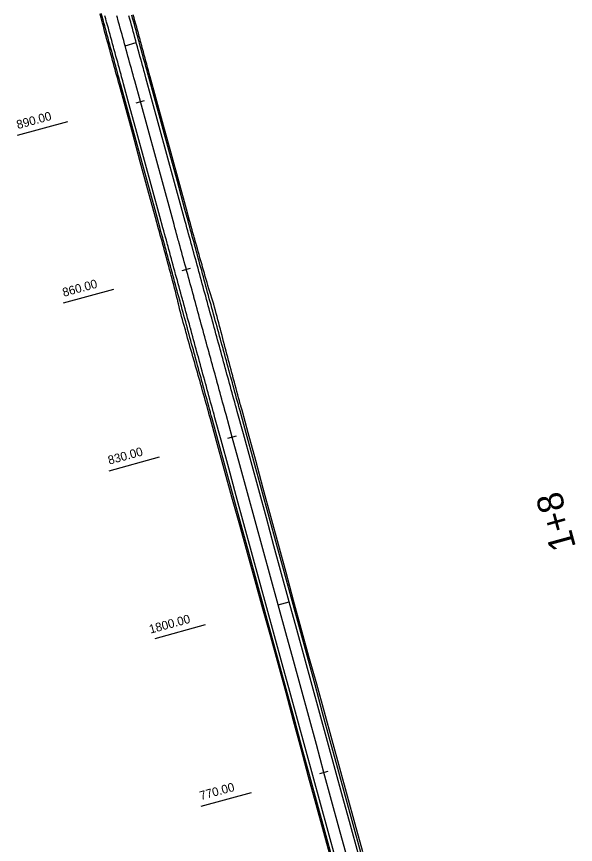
# Model space of a CAD drawing. Extents: x -550605 to -538780, y -1102367 to -1093705.
# Drawn here: x -547558.2 to -547461.7, y -1100514.3 to -1100371.5 of the extents above; entities that cross this region are included whole.
import ezdxf

# ---------------------------------------------------------------- set-up
doc = ezdxf.new("R2010")
doc.units = 0
for name, color, linetype in [('SIT - hrany vozovky', 7, 'Continuous'), ('SIT - osa cesty', 7, 'Continuous'), ('SIT - paty násypů', 7, 'Continuous'), ('SIT - staničení po 100m', 7, 'Continuous'), ('SIT - staničení po 30m', 7, 'Continuous')]:
    doc.layers.add(name, color=color, linetype=linetype)

msp = doc.modelspace()

# ---------------------------------------------------------------- linework, layer by layer
at = {"layer": 'SIT - hrany vozovky'}
for points in [[(-547503.59, -1100517.03), (-547504.91, -1100512.21), (-547506.23, -1100507.39), (-547507.55, -1100502.56), (-547508.87, -1100497.74), (-547510.19, -1100492.92), (-547511.51, -1100488.09), (-547512.83, -1100483.27), (-547514.15, -1100478.45), (-547515.47, -1100473.63), (-547516.79, -1100468.8), (-547518.11, -1100463.98), (-547519.43, -1100459.16), (-547520.74, -1100454.34), (-547522.06, -1100449.51), (-547523.38, -1100444.69), (-547524.44, -1100440.83), (-547524.59, -1100440.29), (-547524.7, -1100439.87), (-547524.74, -1100439.75), (-547524.88, -1100439.22), (-547525.03, -1100438.68), (-547525.18, -1100438.14), (-547525.32, -1100437.6), (-547525.47, -1100437.07), (-547525.62, -1100436.53), (-547525.77, -1100435.99), (-547525.91, -1100435.45), (-547526.02, -1100435.05), (-547526.06, -1100434.92), (-547526.21, -1100434.38), (-547526.35, -1100433.84), (-547526.5, -1100433.3), (-547526.65, -1100432.77), (-547526.8, -1100432.23), (-547526.94, -1100431.69), (-547527.09, -1100431.15), (-547527.24, -1100430.62), (-547527.34, -1100430.22), (-547527.38, -1100430.08), (-547527.53, -1100429.54), (-547527.68, -1100429), (-547527.83, -1100428.47), (-547527.97, -1100427.93), (-547528.12, -1100427.39), (-547528.27, -1100426.85), (-547528.41, -1100426.32), (-547528.56, -1100425.78), (-547528.66, -1100425.4), (-547528.71, -1100425.24), (-547528.86, -1100424.7), (-547529, -1100424.17), (-547529.15, -1100423.63), (-547529.3, -1100423.09), (-547529.44, -1100422.56), (-547529.59, -1100422.02), (-547529.74, -1100421.48), (-547529.88, -1100420.94), (-547529.98, -1100420.58), (-547530.03, -1100420.41), (-547530.18, -1100419.87), (-547530.33, -1100419.33), (-547530.47, -1100418.79), (-547530.62, -1100418.26), (-547530.77, -1100417.72), (-547530.91, -1100417.18), (-547531.06, -1100416.64), (-547531.21, -1100416.11), (-547531.3, -1100415.76), (-547531.36, -1100415.57), (-547531.5, -1100415.03), (-547531.65, -1100414.49), (-547531.8, -1100413.96), (-547531.94, -1100413.42), (-547532.09, -1100412.88), (-547532.24, -1100412.34), (-547532.39, -1100411.81), (-547532.53, -1100411.27), (-547532.62, -1100410.93), (-547532.68, -1100410.73), (-547532.83, -1100410.19), (-547532.97, -1100409.66), (-547533.12, -1100409.12), (-547533.27, -1100408.58), (-547533.42, -1100408.04), (-547533.94, -1100406.11), (-547535.26, -1100401.29), (-547536.58, -1100396.47), (-547537.9, -1100391.64), (-547539.22, -1100386.82), (-547540.2, -1100383.25), (-547540.35, -1100382.71), (-547540.49, -1100382.18), (-547540.54, -1100382), (-547540.64, -1100381.64), (-547540.79, -1100381.11), (-547540.93, -1100380.58), (-547541.08, -1100380.04), (-547541.23, -1100379.51), (-547541.37, -1100378.97), (-547541.52, -1100378.44), (-547541.66, -1100377.91), (-547541.81, -1100377.37), (-547541.86, -1100377.17), (-547541.96, -1100376.84), (-547542.1, -1100376.3), (-547542.25, -1100375.77), (-547542.39, -1100375.24), (-547542.54, -1100374.7), (-547542.69, -1100374.17), (-547542.83, -1100373.63), (-547542.98, -1100373.1), (-547543.13, -1100372.57), (-547543.18, -1100372.35), (-547543.27, -1100372.03), (-547543.42, -1100371.5), (-547543.56, -1100370.97)], [(-547503.1, -1100516.9), (-547504.42, -1100512.08), (-547505.74, -1100507.25), (-547507.06, -1100502.43), (-547508.38, -1100497.61), (-547509.7, -1100492.79), (-547511.02, -1100487.96), (-547512.34, -1100483.14), (-547513.66, -1100478.32), (-547514.98, -1100473.5), (-547516.3, -1100468.67), (-547517.62, -1100463.85), (-547518.94, -1100459.03), (-547520.26, -1100454.2), (-547521.58, -1100449.38), (-547522.9, -1100444.56), (-547523.96, -1100440.7), (-547524.11, -1100440.16), (-547524.22, -1100439.74), (-547524.25, -1100439.62), (-547524.4, -1100439.09), (-547524.55, -1100438.55), (-547524.7, -1100438.01), (-547524.84, -1100437.47), (-547524.99, -1100436.94), (-547525.14, -1100436.4), (-547525.28, -1100435.86), (-547525.43, -1100435.32), (-547525.54, -1100434.91), (-547525.58, -1100434.79), (-547525.72, -1100434.25), (-547525.87, -1100433.71), (-547526.02, -1100433.17), (-547526.17, -1100432.64), (-547526.31, -1100432.1), (-547526.46, -1100431.56), (-547526.61, -1100431.02), (-547526.75, -1100430.49), (-547526.86, -1100430.09), (-547526.9, -1100429.95), (-547527.05, -1100429.41), (-547527.2, -1100428.87), (-547527.34, -1100428.34), (-547527.49, -1100427.8), (-547527.64, -1100427.26), (-547527.78, -1100426.72), (-547527.93, -1100426.19), (-547528.08, -1100425.65), (-547528.18, -1100425.27), (-547528.23, -1100425.11), (-547528.37, -1100424.57), (-547528.52, -1100424.04), (-547528.67, -1100423.5), (-547528.81, -1100422.96), (-547528.96, -1100422.42), (-547529.11, -1100421.89), (-547529.26, -1100421.35), (-547529.4, -1100420.81), (-547529.5, -1100420.45), (-547529.55, -1100420.27), (-547529.7, -1100419.74), (-547529.84, -1100419.2), (-547529.99, -1100418.66), (-547530.14, -1100418.12), (-547530.29, -1100417.59), (-547530.43, -1100417.05), (-547530.58, -1100416.51), (-547530.73, -1100415.97), (-547530.82, -1100415.62), (-547530.87, -1100415.44), (-547531.02, -1100414.9), (-547531.17, -1100414.36), (-547531.32, -1100413.82), (-547531.46, -1100413.29), (-547531.61, -1100412.75), (-547531.76, -1100412.21), (-547531.9, -1100411.67), (-547532.05, -1100411.14), (-547532.14, -1100410.8), (-547532.2, -1100410.6), (-547532.34, -1100410.06), (-547532.49, -1100409.52), (-547532.64, -1100408.99), (-547532.79, -1100408.45), (-547532.93, -1100407.91), (-547533.46, -1100405.98), (-547534.78, -1100401.16), (-547536.1, -1100396.33), (-547537.42, -1100391.51), (-547538.74, -1100386.69), (-547539.72, -1100383.11), (-547539.87, -1100382.58), (-547540.01, -1100382.05), (-547540.06, -1100381.87), (-547540.16, -1100381.51), (-547540.3, -1100380.98), (-547540.45, -1100380.44), (-547540.6, -1100379.91), (-547540.74, -1100379.38), (-547540.89, -1100378.84), (-547541.04, -1100378.31), (-547541.18, -1100377.77), (-547541.33, -1100377.24), (-547541.38, -1100377.04), (-547541.47, -1100376.71), (-547541.62, -1100376.17), (-547541.77, -1100375.64), (-547541.91, -1100375.1), (-547542.06, -1100374.57), (-547542.2, -1100374.04), (-547542.35, -1100373.5), (-547542.5, -1100372.97), (-547542.64, -1100372.43), (-547542.7, -1100372.22), (-547542.79, -1100371.9), (-547542.94, -1100371.37)], [(-547499.25, -1100515.84), (-547500.57, -1100511.02), (-547501.89, -1100506.2), (-547503.21, -1100501.37), (-547504.53, -1100496.55), (-547505.84, -1100491.73), (-547507.16, -1100486.91), (-547508.48, -1100482.08), (-547509.8, -1100477.26), (-547511.12, -1100472.44), (-547512.44, -1100467.62), (-547513.76, -1100462.79), (-547515.08, -1100457.97), (-547516.4, -1100453.15), (-547517.72, -1100448.33), (-547519.04, -1100443.5), (-547520.1, -1100439.64), (-547520.25, -1100439.1), (-547520.36, -1100438.68), (-547520.4, -1100438.57), (-547520.54, -1100438.03), (-547520.69, -1100437.49), (-547520.84, -1100436.95), (-547520.98, -1100436.42), (-547521.13, -1100435.88), (-547521.28, -1100435.34), (-547521.43, -1100434.8), (-547521.57, -1100434.27), (-547521.68, -1100433.86), (-547521.72, -1100433.73), (-547521.87, -1100433.19), (-547522.01, -1100432.65), (-547522.16, -1100432.12), (-547522.31, -1100431.58), (-547522.46, -1100431.04), (-547522.6, -1100430.5), (-547522.75, -1100429.97), (-547522.9, -1100429.43), (-547523, -1100429.04), (-547523.04, -1100428.89), (-547523.19, -1100428.35), (-547523.34, -1100427.82), (-547523.49, -1100427.28), (-547523.63, -1100426.74), (-547523.78, -1100426.2), (-547523.93, -1100425.67), (-547524.07, -1100425.13), (-547524.22, -1100424.59), (-547524.32, -1100424.21), (-547524.37, -1100424.05), (-547524.51, -1100423.52), (-547524.66, -1100422.98), (-547524.81, -1100422.44), (-547524.96, -1100421.9), (-547525.1, -1100421.37), (-547525.25, -1100420.83), (-547525.4, -1100420.29), (-547525.54, -1100419.75), (-547525.64, -1100419.39), (-547525.69, -1100419.22), (-547525.84, -1100418.68), (-547525.99, -1100418.14), (-547526.13, -1100417.6), (-547526.28, -1100417.07), (-547526.43, -1100416.53), (-547526.57, -1100415.99), (-547526.72, -1100415.45), (-547526.87, -1100414.92), (-547526.96, -1100414.57), (-547527.02, -1100414.38), (-547527.16, -1100413.84), (-547527.31, -1100413.3), (-547527.46, -1100412.77), (-547527.6, -1100412.23), (-547527.75, -1100411.69), (-547527.9, -1100411.15), (-547528.05, -1100410.62), (-547528.19, -1100410.08), (-547528.28, -1100409.74), (-547528.34, -1100409.54), (-547528.49, -1100409), (-547528.63, -1100408.47), (-547528.78, -1100407.93), (-547528.93, -1100407.39), (-547529.08, -1100406.85), (-547529.6, -1100404.92), (-547530.92, -1100400.1), (-547532.24, -1100395.28), (-547533.56, -1100390.45), (-547534.88, -1100385.63), (-547535.86, -1100382.06), (-547536.01, -1100381.52), (-547536.15, -1100380.99), (-547536.2, -1100380.81), (-547536.3, -1100380.46), (-547536.45, -1100379.92), (-547536.59, -1100379.39), (-547536.74, -1100378.85), (-547536.89, -1100378.32), (-547537.03, -1100377.79), (-547537.18, -1100377.25), (-547537.32, -1100376.72), (-547537.47, -1100376.18), (-547537.52, -1100375.99), (-547537.62, -1100375.65), (-547537.76, -1100375.12), (-547537.91, -1100374.58), (-547538.05, -1100374.05), (-547538.2, -1100373.51), (-547538.35, -1100372.98), (-547538.49, -1100372.45), (-547538.64, -1100371.91), (-547538.79, -1100371.38)], [(-547498.76, -1100515.71), (-547500.08, -1100510.89), (-547501.4, -1100506.07), (-547502.72, -1100501.24), (-547504.04, -1100496.42), (-547505.36, -1100491.6), (-547506.68, -1100486.77), (-547508, -1100481.95), (-547509.32, -1100477.13), (-547510.64, -1100472.31), (-547511.96, -1100467.48), (-547513.28, -1100462.66), (-547514.6, -1100457.84), (-547515.92, -1100453.02), (-547517.24, -1100448.19), (-547518.56, -1100443.37), (-547519.62, -1100439.51), (-547519.77, -1100438.97), (-547519.88, -1100438.55), (-547519.91, -1100438.43), (-547520.06, -1100437.9), (-547520.21, -1100437.36), (-547520.35, -1100436.82), (-547520.5, -1100436.28), (-547520.65, -1100435.75), (-547520.8, -1100435.21), (-547520.94, -1100434.67), (-547521.09, -1100434.13), (-547521.2, -1100433.73), (-547521.24, -1100433.6), (-547521.38, -1100433.06), (-547521.53, -1100432.52), (-547521.68, -1100431.98), (-547521.83, -1100431.45), (-547521.97, -1100430.91), (-547522.12, -1100430.37), (-547522.27, -1100429.84), (-547522.41, -1100429.3), (-547522.52, -1100428.9), (-547522.56, -1100428.76), (-547522.71, -1100428.22), (-547522.86, -1100427.69), (-547523, -1100427.15), (-547523.15, -1100426.61), (-547523.3, -1100426.07), (-547523.44, -1100425.54), (-547523.59, -1100425), (-547523.74, -1100424.46), (-547523.84, -1100424.08), (-547523.89, -1100423.92), (-547524.03, -1100423.39), (-547524.18, -1100422.85), (-547524.33, -1100422.31), (-547524.47, -1100421.77), (-547524.62, -1100421.24), (-547524.77, -1100420.7), (-547524.92, -1100420.16), (-547525.06, -1100419.62), (-547525.16, -1100419.26), (-547525.21, -1100419.09), (-547525.36, -1100418.55), (-547525.5, -1100418.01), (-547525.65, -1100417.47), (-547525.8, -1100416.94), (-547525.95, -1100416.4), (-547526.09, -1100415.86), (-547526.24, -1100415.32), (-547526.39, -1100414.79), (-547526.48, -1100414.44), (-547526.53, -1100414.25), (-547526.68, -1100413.71), (-547526.83, -1100413.17), (-547526.97, -1100412.64), (-547527.12, -1100412.1), (-547527.27, -1100411.56), (-547527.42, -1100411.02), (-547527.56, -1100410.49), (-547527.71, -1100409.95), (-547527.8, -1100409.61), (-547527.86, -1100409.41), (-547528, -1100408.87), (-547528.15, -1100408.34), (-547528.3, -1100407.8), (-547528.45, -1100407.26), (-547528.59, -1100406.72), (-547529.12, -1100404.79), (-547530.44, -1100399.97), (-547531.76, -1100395.15), (-547533.08, -1100390.32), (-547534.4, -1100385.5), (-547535.38, -1100381.93), (-547535.53, -1100381.39), (-547535.67, -1100380.86), (-547535.72, -1100380.68), (-547535.82, -1100380.32), (-547535.96, -1100379.79), (-547536.11, -1100379.26), (-547536.26, -1100378.72), (-547536.4, -1100378.19), (-547536.55, -1100377.65), (-547536.7, -1100377.12), (-547536.84, -1100376.59), (-547536.99, -1100376.05), (-547537.04, -1100375.85), (-547537.13, -1100375.52), (-547537.28, -1100374.98), (-547537.43, -1100374.45), (-547537.57, -1100373.92), (-547537.72, -1100373.38), (-547537.86, -1100372.85), (-547538.01, -1100372.31), (-547538.16, -1100371.78), (-547538.3, -1100371.25)]]:
    msp.add_lwpolyline(points, dxfattribs=at)
at = {"layer": 'SIT - osa cesty'}
msp.add_lwpolyline([(-547501.17, -1100516.37), (-547502.49, -1100511.55), (-547503.81, -1100506.73), (-547505.13, -1100501.9), (-547506.45, -1100497.08), (-547507.77, -1100492.26), (-547509.09, -1100487.43), (-547510.41, -1100482.61), (-547511.73, -1100477.79), (-547513.05, -1100472.97), (-547514.37, -1100468.14), (-547515.69, -1100463.32), (-547517.01, -1100458.5), (-547518.33, -1100453.68), (-547519.65, -1100448.85), (-547520.97, -1100444.03), (-547522.03, -1100440.17), (-547522.18, -1100439.63), (-547522.29, -1100439.21), (-547522.32, -1100439.09), (-547522.47, -1100438.56), (-547522.62, -1100438.02), (-547522.77, -1100437.48), (-547522.91, -1100436.94), (-547523.06, -1100436.41), (-547523.21, -1100435.87), (-547523.35, -1100435.33), (-547523.5, -1100434.79), (-547523.61, -1100434.39), (-547523.65, -1100434.26), (-547523.8, -1100433.72), (-547523.94, -1100433.18), (-547524.09, -1100432.64), (-547524.24, -1100432.11), (-547524.38, -1100431.57), (-547524.53, -1100431.03), (-547524.68, -1100430.49), (-547524.83, -1100429.96), (-547524.93, -1100429.56), (-547524.97, -1100429.42), (-547525.12, -1100428.88), (-547525.27, -1100428.34), (-547525.41, -1100427.81), (-547525.56, -1100427.27), (-547525.71, -1100426.73), (-547525.86, -1100426.2), (-547526, -1100425.66), (-547526.15, -1100425.12), (-547526.25, -1100424.74), (-547526.3, -1100424.58), (-547526.44, -1100424.05), (-547526.59, -1100423.51), (-547526.74, -1100422.97), (-547526.89, -1100422.43), (-547527.03, -1100421.9), (-547527.18, -1100421.36), (-547527.33, -1100420.82), (-547527.47, -1100420.28), (-547527.57, -1100419.92), (-547527.62, -1100419.75), (-547527.77, -1100419.21), (-547527.91, -1100418.67), (-547528.06, -1100418.13), (-547528.21, -1100417.6), (-547528.36, -1100417.06), (-547528.5, -1100416.52), (-547528.65, -1100415.98), (-547528.8, -1100415.45), (-547528.89, -1100415.1), (-547528.94, -1100414.91), (-547529.09, -1100414.37), (-547529.24, -1100413.83), (-547529.39, -1100413.3), (-547529.53, -1100412.76), (-547529.68, -1100412.22), (-547529.83, -1100411.68), (-547529.97, -1100411.15), (-547530.12, -1100410.61), (-547530.21, -1100410.27), (-547530.27, -1100410.07), (-547530.42, -1100409.53), (-547530.56, -1100409), (-547530.71, -1100408.46), (-547530.86, -1100407.92), (-547531, -1100407.38), (-547531.53, -1100405.45), (-547532.85, -1100400.63), (-547534.17, -1100395.81), (-547535.49, -1100390.98), (-547536.81, -1100386.16), (-547537.79, -1100382.59), (-547537.94, -1100382.05), (-547538.08, -1100381.52), (-547538.13, -1100381.34), (-547538.23, -1100380.98), (-547538.38, -1100380.45), (-547538.52, -1100379.92), (-547538.67, -1100379.38), (-547538.81, -1100378.85), (-547538.96, -1100378.31), (-547539.11, -1100377.78), (-547539.25, -1100377.25), (-547539.4, -1100376.71), (-547539.45, -1100376.51), (-547539.55, -1100376.18), (-547539.69, -1100375.64), (-547539.84, -1100375.11), (-547539.98, -1100374.58), (-547540.13, -1100374.04), (-547540.28, -1100373.51), (-547540.42, -1100372.97), (-547540.57, -1100372.44), (-547540.71, -1100371.91), (-547540.77, -1100371.69), (-547540.86, -1100371.37)], dxfattribs=at)
at = {"layer": 'SIT - paty násypů'}
for points in [[(-547503.86, -1100517.11), (-547505.17, -1100512.28), (-547506.47, -1100507.45), (-547507.78, -1100502.63), (-547509.08, -1100497.8), (-547510.38, -1100492.97), (-547511.66, -1100488.14), (-547512.98, -1100483.32), (-547514.33, -1100478.5), (-547515.67, -1100473.68), (-547517.01, -1100468.86), (-547518.34, -1100464.05), (-547519.68, -1100459.23), (-547521.02, -1100454.41), (-547522.35, -1100449.59), (-547523.67, -1100444.77), (-547524.73, -1100440.91), (-547524.88, -1100440.37), (-547525, -1100439.95), (-547525.03, -1100439.83), (-547525.18, -1100439.3), (-547525.32, -1100438.76), (-547525.47, -1100438.22), (-547525.62, -1100437.69), (-547525.77, -1100437.15), (-547525.92, -1100436.61), (-547526.07, -1100436.08), (-547526.22, -1100435.54), (-547526.33, -1100435.13), (-547526.37, -1100435), (-547526.52, -1100434.46), (-547526.67, -1100433.93), (-547526.82, -1100433.39), (-547526.97, -1100432.86), (-547527.12, -1100432.32), (-547527.28, -1100431.78), (-547527.43, -1100431.25), (-547527.59, -1100430.71), (-547527.7, -1100430.32), (-547527.75, -1100430.18), (-547527.9, -1100429.64), (-547528.06, -1100429.11), (-547528.21, -1100428.57), (-547528.36, -1100428.04), (-547528.51, -1100427.5), (-547528.66, -1100426.96), (-547528.81, -1100426.42), (-547528.96, -1100425.89), (-547529.06, -1100425.51), (-547529.11, -1100425.35), (-547529.26, -1100424.81), (-547529.41, -1100424.28), (-547529.56, -1100423.74), (-547529.71, -1100423.21), (-547529.86, -1100422.67), (-547529.99, -1100422.13), (-547530.11, -1100421.58), (-547530.25, -1100421.04), (-547530.34, -1100420.67), (-547530.38, -1100420.5), (-547530.51, -1100419.96), (-547530.64, -1100419.42), (-547530.78, -1100418.88), (-547530.91, -1100418.33), (-547531.05, -1100417.8), (-547531.2, -1100417.26), (-547531.34, -1100416.72), (-547531.49, -1100416.18), (-547531.58, -1100415.83), (-547531.63, -1100415.64), (-547531.77, -1100415.1), (-547531.92, -1100414.57), (-547532.06, -1100414.03), (-547532.21, -1100413.49), (-547532.35, -1100412.95), (-547532.5, -1100412.41), (-547532.65, -1100411.88), (-547532.79, -1100411.34), (-547532.88, -1100411), (-547532.94, -1100410.8), (-547533.08, -1100410.26), (-547533.23, -1100409.73), (-547533.38, -1100409.19), (-547533.52, -1100408.65), (-547533.67, -1100408.11), (-547534.2, -1100406.18), (-547535.52, -1100401.36), (-547536.84, -1100396.54), (-547538.15, -1100391.71), (-547539.46, -1100386.89), (-547540.45, -1100383.31), (-547540.6, -1100382.78), (-547540.74, -1100382.25), (-547540.79, -1100382.07), (-547540.89, -1100381.71), (-547541.04, -1100381.18), (-547541.18, -1100380.64), (-547541.33, -1100380.11), (-547541.48, -1100379.58), (-547541.62, -1100379.04), (-547541.77, -1100378.51), (-547541.91, -1100377.97), (-547542.06, -1100377.44), (-547542.11, -1100377.24), (-547542.2, -1100376.91), (-547542.35, -1100376.37), (-547542.49, -1100375.84), (-547542.64, -1100375.3), (-547542.78, -1100374.77), (-547542.93, -1100374.23), (-547543.07, -1100373.7), (-547543.21, -1100373.16), (-547543.36, -1100372.63), (-547543.41, -1100372.41), (-547543.5, -1100372.1), (-547543.64, -1100371.56), (-547543.78, -1100371.03)], [(-547498.43, -1100515.62), (-547499.75, -1100510.8), (-547501.07, -1100505.98), (-547502.4, -1100501.15), (-547503.72, -1100496.33), (-547505.04, -1100491.51), (-547506.37, -1100486.69), (-547507.73, -1100481.88), (-547509.07, -1100477.06), (-547510.38, -1100472.23), (-547511.68, -1100467.41), (-547512.99, -1100462.58), (-547514.3, -1100457.76), (-547515.6, -1100452.93), (-547516.91, -1100448.1), (-547518.22, -1100443.28), (-547519.28, -1100439.42), (-547519.42, -1100438.88), (-547519.54, -1100438.45), (-547519.57, -1100438.34), (-547519.71, -1100437.8), (-547519.86, -1100437.26), (-547520.01, -1100436.73), (-547520.15, -1100436.19), (-547520.3, -1100435.65), (-547520.44, -1100435.11), (-547520.59, -1100434.57), (-547520.73, -1100434.04), (-547520.84, -1100433.63), (-547520.87, -1100433.5), (-547521.02, -1100432.96), (-547521.16, -1100432.42), (-547521.31, -1100431.88), (-547521.45, -1100431.34), (-547521.59, -1100430.81), (-547521.74, -1100430.27), (-547521.88, -1100429.73), (-547522.02, -1100429.19), (-547522.13, -1100428.8), (-547522.17, -1100428.65), (-547522.31, -1100428.11), (-547522.45, -1100427.57), (-547522.59, -1100427.04), (-547522.73, -1100426.5), (-547522.88, -1100425.96), (-547523.02, -1100425.42), (-547523.16, -1100424.88), (-547523.3, -1100424.34), (-547523.4, -1100423.96), (-547523.44, -1100423.8), (-547523.58, -1100423.26), (-547523.72, -1100422.72), (-547523.86, -1100422.18), (-547524.01, -1100421.64), (-547524.17, -1100421.11), (-547524.34, -1100420.58), (-547524.5, -1100420.05), (-547524.66, -1100419.51), (-547524.78, -1100419.15), (-547524.83, -1100418.98), (-547524.99, -1100418.45), (-547525.16, -1100417.91), (-547525.32, -1100417.38), (-547525.48, -1100416.85), (-547525.63, -1100416.31), (-547525.78, -1100415.78), (-547525.94, -1100415.24), (-547526.09, -1100414.7), (-547526.18, -1100414.35), (-547526.24, -1100414.17), (-547526.39, -1100413.63), (-547526.54, -1100413.09), (-547526.69, -1100412.56), (-547526.84, -1100412.02), (-547526.99, -1100411.48), (-547527.14, -1100410.95), (-547527.29, -1100410.41), (-547527.44, -1100409.87), (-547527.53, -1100409.54), (-547527.59, -1100409.34), (-547527.74, -1100408.8), (-547527.89, -1100408.26), (-547528.03, -1100407.73), (-547528.18, -1100407.19), (-547528.33, -1100406.65), (-547528.86, -1100404.72), (-547530.19, -1100399.9), (-547531.52, -1100395.08), (-547532.85, -1100390.26), (-547534.17, -1100385.44), (-547535.13, -1100381.86), (-547535.28, -1100381.32), (-547535.42, -1100380.79), (-547535.47, -1100380.61), (-547535.57, -1100380.25), (-547535.71, -1100379.72), (-547535.86, -1100379.19), (-547536, -1100378.65), (-547536.15, -1100378.12), (-547536.29, -1100377.58), (-547536.44, -1100377.05), (-547536.58, -1100376.51), (-547536.73, -1100375.98), (-547536.78, -1100375.78), (-547536.87, -1100375.45), (-547537.02, -1100374.91), (-547537.17, -1100374.38), (-547537.31, -1100373.85), (-547537.46, -1100373.31), (-547537.61, -1100372.78), (-547537.75, -1100372.24), (-547537.9, -1100371.71), (-547538.05, -1100371.18)]]:
    msp.add_lwpolyline(points, dxfattribs=at)
at = {"layer": 'SIT - staničení po 100m'}
for points in [[(-547539.45, -1100376.51), (-547537.52, -1100375.99)], [(-547513.05, -1100472.97), (-547511.12, -1100472.44)]]:
    msp.add_lwpolyline(points, dxfattribs=at)
at = {"layer": 'SIT - staničení po 30m'}
for points in [[(-547537.54, -1100386.36), (-547536.09, -1100385.96)], [(-547558.03, -1100391.97), (-547549.35, -1100389.59)], [(-547529.62, -1100415.29), (-547528.17, -1100414.9)], [(-547550.11, -1100420.9), (-547541.43, -1100418.53)], [(-547521.7, -1100444.23), (-547520.25, -1100443.83)], [(-547542.19, -1100449.84), (-547533.51, -1100447.46)], [(-547534.27, -1100478.77), (-547525.59, -1100476.4)], [(-547505.86, -1100502.1), (-547504.41, -1100501.7)], [(-547526.35, -1100507.71), (-547517.67, -1100505.33)]]:
    msp.add_lwpolyline(points, dxfattribs=at)

# ---------------------------------------------------------------- texts
at = {"layer": 'SIT - staničení po 100m'}
msp.add_text('1+8', height=4.5, rotation=105.307, dxfattribs=at).set_placement((-547461.61, -1100463))
at = {"layer": 'SIT - staničení po 30m'}
for s, p in [('890.00', (-547557.96, -1100390.91)), ('860.00', (-547550.04, -1100419.85)), ('830.00', (-547542.19, -1100448.8)), ('1800.00', (-547535.08, -1100477.96)), ('770.00', (-547526.37, -1100506.68))]:
    msp.add_text(s, height=1.5, rotation=15.307, dxfattribs=at).set_placement(p)

doc.saveas('drawing.dxf')
